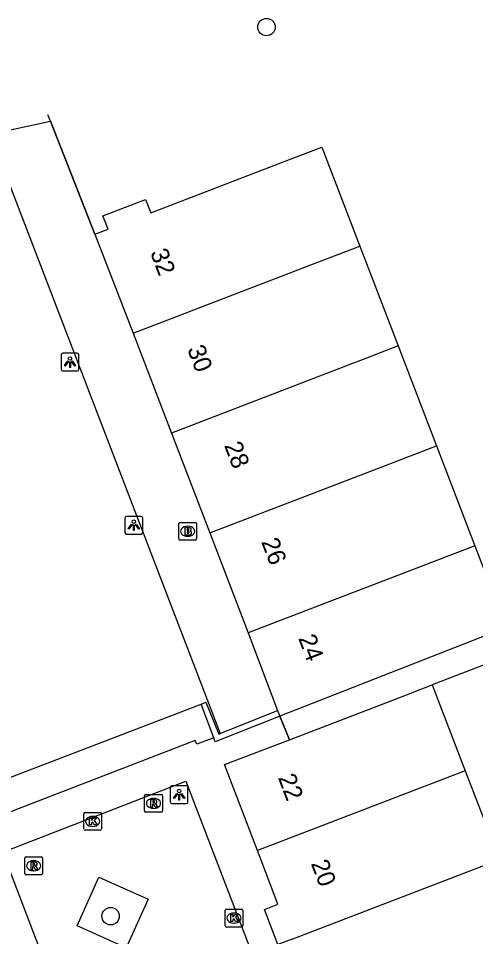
# Model space of a CAD drawing. Extents: x 159265 to 160143, y 383413 to 384319.
# Drawn here: x 159588.2 to 159613.8, y 383679.8 to 383731.3 of the extents above; entities that cross this region are included whole.
import ezdxf

# ---------------------------------------------------------------- set-up
doc = ezdxf.new("R2010")
doc.units = 0
for name, color, linetype in [('IMGEO_Boom', 7, 'Continuous'), ('IMGEO_Brandkraan', 7, 'Continuous'), ('IMGEO_Hek', 7, 'Continuous'), ('IMGEO_Kolk', 7, 'Continuous'), ('IMGEO_Lichtpunt', 7, 'Continuous'), ('IMGEO_Muur', 7, 'Continuous'), ('IMGEO_Pand', 7, 'Continuous'), ('IMGEO_Pand_nummerreeks', 7, 'Continuous'), ('IMGEO_Rioolput', 7, 'Continuous'), ('IMGEO_Voetpad_gesloten', 7, 'Continuous'), ('IMGEO_Voetpad_open', 7, 'Continuous')]:
    doc.layers.add(name, color=color, linetype=linetype)

msp = doc.modelspace()

# ---------------------------------------------------------------- linework, layer by layer
at = {"layer": 'IMGEO_Boom'}
for centre in [(159602.092, 383730.792), (159593.352, 383680.959)]:
    msp.add_circle(centre, 0.489, dxfattribs=at)
at = {"layer": 'IMGEO_Brandkraan'}
for p, q in [((159597.175, 383702.107), (159597.175, 383702.959)), ((159597.25, 383703.033), (159598.102, 383703.033)), ((159597.663, 383702.813), (159597.688, 383702.813)), ((159598.176, 383702.959), (159598.176, 383702.107)), ((159597.686, 383702.253), (159597.661, 383702.253)), ((159598.102, 383702.033), (159597.25, 383702.033))]:
    msp.add_line(p, q, dxfattribs=at)
for points in [[(159597.175, 383702.107), (159597.175, 383702.959)], [(159597.25, 383703.033), (159598.102, 383703.033)], [(159597.523, 383702.733), (159597.523, 383702.333), (159597.736, 383702.333)], [(159597.754, 383702.733), (159597.523, 383702.733)], [(159597.702, 383702.652), (159597.648, 383702.652), (159597.648, 383702.576)], [(159598.176, 383702.959), (159598.176, 383702.107)], [(159597.648, 383702.576), (159597.701, 383702.576)], [(159597.71, 383702.5), (159597.648, 383702.5), (159597.648, 383702.419)], [(159597.648, 383702.419), (159597.71, 383702.419)], [(159598.102, 383702.033), (159597.25, 383702.033)]]:
    msp.add_lwpolyline(points, dxfattribs=at)
for centre, radius, start, end in [((159597.252, 383702.957), 0.0765, 91.552, 178.448), ((159597.252, 383702.957), 0.0765, 91.552, 178.448), ((159597.703, 383702.614), 0.0379, 267.8285, 90.9355), ((159597.758, 383702.588), 0.145, 59.4692, 91.5367), ((159597.783, 383702.635), 0.0922, 285.5137, 58.1501), ((159598.1, 383702.957), 0.0765, 1.552, 88.448), ((159598.1, 383702.957), 0.0765, 1.552, 88.448), ((159597.252, 383702.109), 0.0765, 181.552, 268.448), ((159597.252, 383702.109), 0.0765, 181.552, 268.448), ((159597.711, 383702.459), 0.0404, 269.8759, 90.5077), ((159597.742, 383702.584), 0.251, 268.6676, 293.5347), ((159597.788, 383702.443), 0.105, 301.3115, 78.989), ((159598.1, 383702.109), 0.0765, 271.552, 358.448), ((159598.1, 383702.109), 0.0765, 271.552, 358.448)]:
    msp.add_arc(centre, radius, start, end, dxfattribs=at)
for centre, major_axis, ratio, start_param, end_param in [((159597.662, 383702.533), (-0.387, 0.002), 0.722429, 4.712389, 7.853982), ((159597.687, 383702.533), (-0.39, 0.002), 0.717154, 1.570796, 4.712389)]:
    msp.add_ellipse(centre, major_axis=major_axis, ratio=ratio, start_param=start_param, end_param=end_param, dxfattribs=at)
at = {"layer": 'IMGEO_Hek'}
msp.add_lwpolyline([(159602.843, 383692.164), (159603.385, 383690.848)], dxfattribs=at)
at = {"layer": 'IMGEO_Kolk'}
for p, q in [((159591.848, 383685.845), (159591.848, 383686.697)), ((159591.923, 383686.771), (159592.775, 383686.771)), ((159592.849, 383686.697), (159592.849, 383685.845)), ((159592.336, 383686.551), (159592.361, 383686.551)), ((159592.775, 383685.771), (159591.923, 383685.771)), ((159592.359, 383685.991), (159592.334, 383685.991)), ((159599.77, 383680.425), (159599.77, 383681.277)), ((159599.845, 383681.351), (159600.697, 383681.351)), ((159600.258, 383681.131), (159600.283, 383681.131)), ((159600.771, 383681.277), (159600.771, 383680.425)), ((159600.281, 383680.571), (159600.256, 383680.571)), ((159600.697, 383680.351), (159599.845, 383680.351))]:
    msp.add_line(p, q, dxfattribs=at)
for points in [[(159591.848, 383685.845), (159591.848, 383686.697)], [(159591.923, 383686.771), (159592.775, 383686.771)], [(159592.849, 383686.697), (159592.849, 383685.845)], [(159592.169, 383686.471), (159592.292, 383686.471), (159592.292, 383686.32), (159592.422, 383686.471), (159592.586, 383686.471), (159592.44, 383686.32), (159592.593, 383686.071), (159592.441, 383686.071), (159592.356, 383686.235), (159592.292, 383686.168), (159592.292, 383686.071), (159592.169, 383686.071), (159592.169, 383686.471)], [(159592.775, 383685.771), (159591.923, 383685.771)], [(159599.77, 383680.425), (159599.77, 383681.277)], [(159599.845, 383681.351), (159600.697, 383681.351)], [(159600.091, 383681.051), (159600.214, 383681.051), (159600.214, 383680.9), (159600.344, 383681.051), (159600.508, 383681.051), (159600.362, 383680.9), (159600.515, 383680.651), (159600.363, 383680.651), (159600.278, 383680.815), (159600.214, 383680.748), (159600.214, 383680.651), (159600.091, 383680.651), (159600.091, 383681.051)], [(159600.771, 383681.277), (159600.771, 383680.425)], [(159600.697, 383680.351), (159599.845, 383680.351)]]:
    msp.add_lwpolyline(points, dxfattribs=at)
for centre, start, end in [((159591.925, 383686.695), 91.552, 178.448), ((159591.925, 383686.695), 91.552, 178.448), ((159592.773, 383686.695), 1.552, 88.448), ((159592.773, 383686.695), 1.552, 88.448), ((159591.925, 383685.847), 181.552, 268.448), ((159591.925, 383685.847), 181.552, 268.448), ((159592.773, 383685.847), 271.552, 358.448), ((159592.773, 383685.847), 271.552, 358.448), ((159599.847, 383681.275), 91.552, 178.448), ((159599.847, 383681.275), 91.552, 178.448), ((159600.695, 383681.275), 1.552, 88.448), ((159600.695, 383681.275), 1.552, 88.448), ((159599.847, 383680.427), 181.552, 268.448), ((159599.847, 383680.427), 181.552, 268.448), ((159600.695, 383680.427), 271.552, 358.448), ((159600.695, 383680.427), 271.552, 358.448)]:
    msp.add_arc(centre, 0.0765, start, end, dxfattribs=at)
for centre, major_axis, ratio, start_param, end_param in [((159592.335, 383686.271), (-0.387, 0.002), 0.722429, 4.712389, 7.853982), ((159592.36, 383686.271), (-0.39, 0.002), 0.717154, 1.570796, 4.712389), ((159600.257, 383680.851), (-0.387, 0.002), 0.722429, 4.712389, 7.853982), ((159600.282, 383680.851), (-0.39, 0.002), 0.717154, 1.570796, 4.712389)]:
    msp.add_ellipse(centre, major_axis=major_axis, ratio=ratio, start_param=start_param, end_param=end_param, dxfattribs=at)
at = {"layer": 'IMGEO_Lichtpunt'}
for p, q in [((159590.583, 383712.418), (159590.583, 383711.611)), ((159590.583, 383712.418), (159590.583, 383711.611)), ((159591.485, 383712.513), (159590.677, 383712.513)), ((159591.485, 383712.513), (159590.677, 383712.513)), ((159591.579, 383711.611), (159591.579, 383712.418)), ((159591.579, 383711.611), (159591.579, 383712.418)), ((159590.677, 383711.517), (159591.485, 383711.517)), ((159590.677, 383711.517), (159591.485, 383711.517)), ((159594.158, 383703.273), (159594.158, 383702.466)), ((159594.158, 383703.273), (159594.158, 383702.466)), ((159595.06, 383703.368), (159594.252, 383703.368)), ((159595.06, 383703.368), (159594.252, 383703.368)), ((159595.154, 383702.466), (159595.154, 383703.273)), ((159595.154, 383702.466), (159595.154, 383703.273)), ((159594.252, 383702.372), (159595.06, 383702.372)), ((159594.252, 383702.372), (159595.06, 383702.372)), ((159597.598, 383688.268), (159596.79, 383688.268)), ((159597.598, 383688.268), (159596.79, 383688.268)), ((159596.696, 383688.173), (159596.696, 383687.366)), ((159596.696, 383688.173), (159596.696, 383687.366)), ((159597.692, 383687.366), (159597.692, 383688.173)), ((159597.692, 383687.366), (159597.692, 383688.173)), ((159596.79, 383687.272), (159597.598, 383687.272)), ((159596.79, 383687.272), (159597.598, 383687.272))]:
    msp.add_line(p, q, dxfattribs=at)
for points in [[(159590.957, 383712.082), (159590.996, 383712.054), (159590.808, 383711.792), (159590.77, 383711.819), (159590.957, 383712.082)], [(159591.059, 383712.034), (159591.106, 383712.034), (159591.106, 383711.712), (159591.059, 383711.712), (159591.059, 383712.034)], [(159591.169, 383712.054), (159591.207, 383712.081), (159591.394, 383711.819), (159591.355, 383711.791), (159591.169, 383712.054)], [(159594.532, 383702.937), (159594.571, 383702.909), (159594.383, 383702.647), (159594.345, 383702.674), (159594.532, 383702.937)], [(159594.634, 383702.889), (159594.681, 383702.889), (159594.681, 383702.567), (159594.634, 383702.567), (159594.634, 383702.889)], [(159594.744, 383702.909), (159594.782, 383702.936), (159594.969, 383702.674), (159594.93, 383702.646), (159594.744, 383702.909)], [(159597.07, 383687.837), (159597.109, 383687.809), (159596.921, 383687.547), (159596.883, 383687.574), (159597.07, 383687.837)], [(159597.172, 383687.789), (159597.219, 383687.789), (159597.219, 383687.467), (159597.172, 383687.467), (159597.172, 383687.789)], [(159597.282, 383687.809), (159597.32, 383687.836), (159597.507, 383687.574), (159597.468, 383687.546), (159597.282, 383687.809)]]:
    msp.add_lwpolyline(points, dxfattribs=at)
for centre in [(159591.082, 383712.216), (159594.657, 383703.071), (159597.195, 383687.971)]:
    msp.add_circle(centre, 0.0994, dxfattribs=at)
for centre, start, end in [((159590.677, 383712.418), 90, 180), ((159590.677, 383712.418), 90, 180), ((159591.485, 383712.418), 0, 90), ((159591.485, 383712.418), 0, 90), ((159590.677, 383711.611), 180, 270), ((159590.677, 383711.611), 180, 270), ((159591.485, 383711.611), 270, 0), ((159591.485, 383711.611), 270, 360), ((159594.252, 383703.273), 90, 180), ((159594.252, 383703.273), 90, 180), ((159595.06, 383703.273), 0, 90), ((159595.06, 383703.273), 0, 90), ((159594.252, 383702.466), 180, 270), ((159594.252, 383702.466), 180, 270), ((159595.06, 383702.466), 270, 0), ((159595.06, 383702.466), 270, 360), ((159596.79, 383688.173), 90, 180), ((159596.79, 383688.173), 90, 180), ((159597.598, 383688.173), 0, 90), ((159597.598, 383688.173), 0, 90), ((159596.79, 383687.366), 180, 270), ((159596.79, 383687.366), 180, 270), ((159597.598, 383687.366), 270, 0), ((159597.598, 383687.366), 270, 360)]:
    msp.add_arc(centre, 0.0946, start, end, dxfattribs=at)
at = {"layer": 'IMGEO_Muur'}
for points in [[(159589.98, 383725.525), (159589.843, 383725.877)], [(159592.463, 383719.183), (159589.98, 383725.525)], [(159598.431, 383692.845), (159598.698, 383692.959), (159599.42, 383691.163), (159599.498, 383691.195)], [(159599.136, 383690.958), (159598.431, 383692.845)], [(159599.498, 383691.195), (159602.706, 383692.496)], [(159602.843, 383692.164), (159599.218, 383690.739), (159599.136, 383690.958)]]:
    msp.add_lwpolyline(points, dxfattribs=at)
at = {"layer": 'IMGEO_Pand'}
for points in [[(159592.463, 383719.183), (159593.21, 383719.47), (159592.923, 383720.217), (159595.313, 383721.134), (159595.6, 383720.387), (159602.753, 383723.134), (159605.194, 383724.071), (159607.325, 383718.52)], [(159592.463, 383719.183), (159594.615, 383713.64)], [(159594.615, 383713.64), (159604.826, 383717.561), (159607.325, 383718.52)], [(159607.325, 383718.52), (159609.477, 383712.918)], [(159594.615, 383713.64), (159596.766, 383708.038)], [(159609.477, 383712.918), (159607.035, 383711.981), (159606.918, 383711.936), (159596.766, 383708.038)], [(159609.477, 383712.918), (159611.628, 383707.317)], [(159596.766, 383708.038), (159598.916, 383702.437)], [(159598.916, 383702.437), (159609.009, 383706.312), (159609.186, 383706.38), (159611.628, 383707.317)], [(159611.628, 383707.317), (159613.778, 383701.717)], [(159598.916, 383702.437), (159601.067, 383696.836)], [(159613.778, 383701.717), (159611.336, 383700.779), (159611.101, 383700.689), (159601.067, 383696.836)], [(159613.778, 383701.717), (159615.536, 383697.14)], [(159615.536, 383697.14), (159613.1, 383696.185), (159602.843, 383692.164)], [(159601.067, 383696.836), (159602.706, 383692.496)], [(159603.385, 383690.848), (159609.277, 383693.11), (159611.383, 383693.919)], [(159611.383, 383693.919), (159613.235, 383689.113)], [(159602.706, 383692.496), (159602.843, 383692.164)], [(159601.593, 383684.643), (159599.747, 383689.451), (159603.385, 383690.848)], [(159613.235, 383689.113), (159601.593, 383684.643)], [(159613.235, 383689.113), (159615.152, 383684.141)], [(159603.468, 383679.655), (159602.732, 383679.372), (159601.984, 383681.333), (159602.729, 383681.628), (159601.593, 383684.643)], [(159603.468, 383679.655), (159615.152, 383684.141)]]:
    msp.add_lwpolyline(points, dxfattribs=at)
at = {"layer": 'IMGEO_Rioolput'}
for p, q in [((159595.257, 383686.857), (159595.257, 383687.709)), ((159595.332, 383687.783), (159596.184, 383687.783)), ((159596.258, 383687.709), (159596.258, 383686.857)), ((159595.745, 383687.563), (159595.77, 383687.563)), ((159596.184, 383686.783), (159595.332, 383686.783)), ((159595.768, 383687.003), (159595.743, 383687.003)), ((159588.541, 383683.357), (159588.541, 383684.209)), ((159588.616, 383684.283), (159589.468, 383684.283)), ((159589.542, 383684.209), (159589.542, 383683.357)), ((159589.029, 383684.063), (159589.054, 383684.063)), ((159589.468, 383683.283), (159588.616, 383683.283)), ((159589.052, 383683.503), (159589.027, 383683.503))]:
    msp.add_line(p, q, dxfattribs=at)
for points in [[(159595.257, 383686.857), (159595.257, 383687.709)], [(159595.332, 383687.783), (159596.184, 383687.783)], [(159596.258, 383687.709), (159596.258, 383686.857)], [(159595.846, 383687.481), (159595.594, 383687.483), (159595.594, 383687.083)], [(159595.594, 383687.083), (159595.718, 383687.083), (159595.718, 383687.245), (159595.729, 383687.245)], [(159595.772, 383687.402), (159595.718, 383687.402), (159595.718, 383687.321)], [(159595.718, 383687.321), (159595.77, 383687.321)], [(159595.776, 383687.216), (159595.847, 383687.083), (159595.987, 383687.083), (159595.922, 383687.209)], [(159596.184, 383686.783), (159595.332, 383686.783)], [(159588.541, 383683.357), (159588.541, 383684.209)], [(159588.616, 383684.283), (159589.468, 383684.283)], [(159589.542, 383684.209), (159589.542, 383683.357)], [(159589.13, 383683.981), (159588.878, 383683.983), (159588.878, 383683.583)], [(159588.878, 383683.583), (159589.002, 383683.583), (159589.002, 383683.745), (159589.013, 383683.745)], [(159589.056, 383683.902), (159589.002, 383683.902), (159589.002, 383683.821)], [(159589.002, 383683.821), (159589.054, 383683.821)], [(159589.06, 383683.716), (159589.131, 383683.583), (159589.271, 383683.583), (159589.206, 383683.709)], [(159589.468, 383683.283), (159588.616, 383683.283)]]:
    msp.add_lwpolyline(points, dxfattribs=at)
for centre, radius, start, end in [((159595.334, 383687.707), 0.0765, 91.552, 178.448), ((159595.334, 383687.707), 0.0765, 91.552, 178.448), ((159596.182, 383687.707), 0.0765, 1.552, 88.448), ((159596.182, 383687.707), 0.0765, 1.552, 88.448), ((159595.728, 383687.192), 0.0533, 26.0293, 88.6989), ((159595.754, 383687.51), 0.19, 274.7715, 282.9687), ((159595.778, 383687.306), 0.0964, 77.0061, 93.1865), ((159595.792, 383687.363), 0.0378, 276.6634, 79.6772), ((159595.845, 383687.371), 0.109, 350.3612, 89.416), ((159595.843, 383687.371), 0.112, 277.5842, 350.9817), ((159595.827, 383687.156), 0.108, 29.5134, 73.7905), ((159595.334, 383686.859), 0.0765, 181.552, 268.448), ((159595.334, 383686.859), 0.0765, 181.552, 268.448), ((159596.182, 383686.859), 0.0765, 271.552, 358.448), ((159596.182, 383686.859), 0.0765, 271.552, 358.448), ((159588.618, 383684.207), 0.0765, 91.552, 178.448), ((159588.618, 383684.207), 0.0765, 91.552, 178.448), ((159589.466, 383684.207), 0.0765, 1.552, 88.448), ((159589.466, 383684.207), 0.0765, 1.552, 88.448), ((159589.012, 383683.692), 0.0533, 26.0293, 88.6989), ((159589.038, 383684.01), 0.19, 274.7715, 282.9687), ((159589.062, 383683.806), 0.0964, 77.0061, 93.1865), ((159589.076, 383683.863), 0.0378, 276.6634, 79.6772), ((159589.129, 383683.871), 0.109, 350.3612, 89.416), ((159589.127, 383683.871), 0.112, 277.5842, 350.9817), ((159589.111, 383683.656), 0.108, 29.5134, 73.7905), ((159588.618, 383683.359), 0.0765, 181.552, 268.448), ((159588.618, 383683.359), 0.0765, 181.552, 268.448), ((159589.466, 383683.359), 0.0765, 271.552, 358.448), ((159589.466, 383683.359), 0.0765, 271.552, 358.448)]:
    msp.add_arc(centre, radius, start, end, dxfattribs=at)
for centre, major_axis, ratio, start_param, end_param in [((159595.744, 383687.283), (-0.387, 0.002), 0.722429, 4.712389, 7.853982), ((159595.769, 383687.283), (-0.39, 0.002), 0.717154, 1.570796, 4.712389), ((159589.028, 383683.783), (-0.387, 0.002), 0.722429, 4.712389, 7.853982), ((159589.053, 383683.783), (-0.39, 0.002), 0.717154, 1.570796, 4.712389)]:
    msp.add_ellipse(centre, major_axis=major_axis, ratio=ratio, start_param=start_param, end_param=end_param, dxfattribs=at)
at = {"layer": 'IMGEO_Voetpad_gesloten'}
for points in [[(159586.575, 383724.788), (159599.498, 383691.195)], [(159585.827, 383688.028), (159598.431, 383692.845)]]:
    msp.add_lwpolyline(points, dxfattribs=at)
at = {"layer": 'IMGEO_Voetpad_open'}
for points in [[(159586.575, 383724.788), (159589.98, 383725.525), (159592.463, 383719.183)], [(159622.807, 383698.104), (159622.811, 383698.309), (159611.383, 383693.919)], [(159603.385, 383690.848), (159602.843, 383692.164)], [(159599.136, 383690.958), (159598.188, 383690.594), (159598.102, 383690.81), (159587.403, 383686.673), (159587.489, 383686.479), (159586.561, 383686.101)], [(159609.011, 383627.739), (159587.311, 383684.551), (159597.575, 383688.534), (159619.379, 383631.734), (159609.011, 383627.739)], [(159594.224, 383679.187), (159591.488, 383680.422), (159592.702, 383683.147), (159595.454, 383681.915), (159594.224, 383679.187)]]:
    msp.add_lwpolyline(points, dxfattribs=at)

# ---------------------------------------------------------------- texts
at = {"layer": 'IMGEO_Pand_nummerreeks'}
for s, rotation, p in [('32', 291.0159, (159595.555, 383718.16)), ('30', 291.0159, (159597.635, 383712.747)), ('28', 291.0159, (159599.711, 383707.343)), ('26', 291.0159, (159601.786, 383701.942)), ('24', 291.0159, (159603.862, 383696.538)), ('22', 290.9717, (159602.724, 383688.726)), ('20', 290.9717, (159604.569, 383683.912))]:
    msp.add_text(s, height=1, rotation=rotation, dxfattribs=at).set_placement(p)

doc.saveas('drawing.dxf')
